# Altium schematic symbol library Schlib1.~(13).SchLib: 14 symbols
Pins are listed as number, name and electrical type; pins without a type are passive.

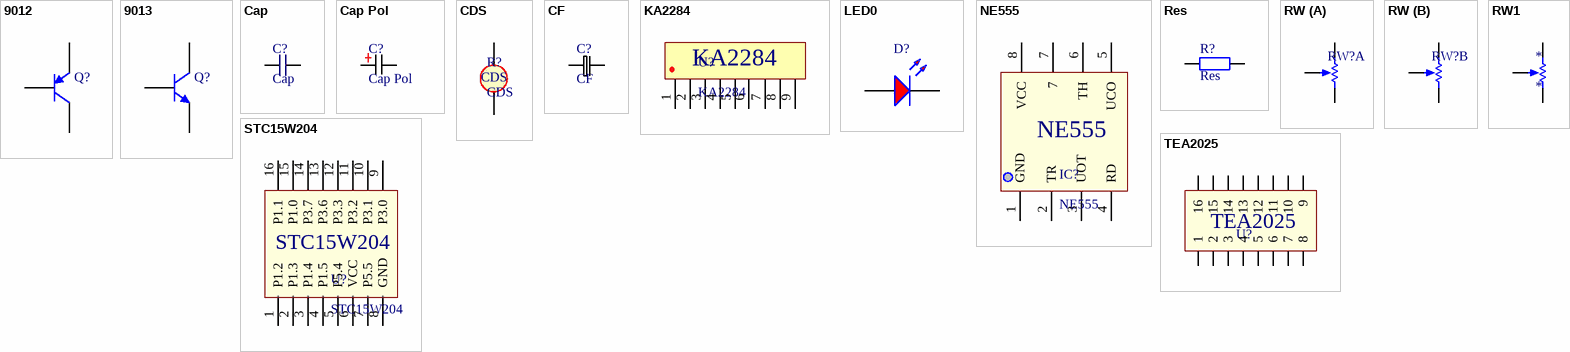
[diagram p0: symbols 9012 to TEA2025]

## 9012
designator Q?  (value not drawn)
PNP General Purpose Amplifier
pins: 1 E, 2 B, 3 C

## 9013
designator Q?  (value not drawn)
NPN General Purpose Amplifier
pins: 1 E, 2 B, 3 C

## Cap
designator C?
pins: 1, 2

## Cap Pol
designator C?
pins: 1, 2

## CDS
designator R?
pins: 1, 2

## CF
designator C?
pins: 1, 2

## KA2284
designator U?
pins: 1, 2, 3, 4, 5, 6, 7, 8, 9

## LED0
designator D?  (value not drawn)
pins: 1 A, 2 K

## NE555
designator IC?
pins: 1 GND, 2 TR, 3 UOT, 4 RD, 5 UCO, 6 TH, 7, 8 VCC

## Res
designator R?
Resistor; Value: 1K
pins: 1, 2

## RW
designator RW?  (value not drawn)
part A pins: 1 TOP, 2 TAP, 3 BOT
part B pins: 4 TOP, 5 TAP, 6 BOT

## RW1
designator *
pins: 1 TOP, 2 TAP, 3 BOT

## STC15W204
designator U?
pins: 1 P1.2, 2 P1.3, 3 P1.4, 4 P1.5, 5 P5.4, 6 VCC, 7 P5.5, 8 GND, 9 P3.0, 10 P3.1, 11 P3.2, 12 P3.3, 13 P3.6, 14 P3.7, 15 P1.0, 16 P1.1

## TEA2025
designator U?  (value not drawn)
pins: 1, 2, 3, 4, 5, 6, 7, 8, 9, 10, 11, 12, 13, 14, 15, 16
